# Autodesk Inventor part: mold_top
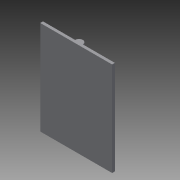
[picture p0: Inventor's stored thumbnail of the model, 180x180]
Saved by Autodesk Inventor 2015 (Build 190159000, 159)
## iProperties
Created: 2015-04
Part Number: mold_top
Material: Generic
Document SubType Name: Modeling
Designer: sungeun
Density: 1 g/cm^3
Appearance: Default
Author: sungeun
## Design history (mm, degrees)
sketch "Sketch1"
  geometry: L1 (-65, -2.5)-(65, -2.5); L2 (65, -2.5)-(65, 2.5); L3 (65, 2.5)-(-65, 2.5); L4 (-65, 2.5)-(-65, -2.5); L5 (-65, -2.5)-(65, 2.5); L6 (65, -2.5)-(-65, 2.5); 1 further point
  constraints: 12 end point, 2 midpoint, 2 parallel, 1 horizontal, 1 perpendicular
  dimensions: "d0" = 130 distance of L2.end L3.end; "d1" = 5 distance of L1.end L2.end
extrude "Extrusion1" new body sketch "Sketch1" stored distance "d2" = 170; taper "d3" = 0 deg
sketch "Sketch2" dims "d20" = 65, "d21" = 45
  geometry: L1 (65, 150)-(65, 20); 2 further points; 1 other entity
  constraints: 2 end point, 1 coincident, 1 vertical, 4 other
  dimensions: "d27" = 130 distance of L1.start L1.end
sketch "Sketch3"
  geometry: L1 (130, 170)-(130, 0) reference; L2 (115, 147.5)-(115, 162.5); A1 r 7.5 centre (115, 155) between (115, 147.5) and (115, 162.5); 1 further point
  constraints: 2 end point, 2 point on circle, 1 centre point, 1 vertical
  dimensions: "d6" = 70 vertical distance of point (65, 85) A1.centre; "d7" = 50 horizontal distance of point (65, 85) A1.centre; "d8" = 15 diameter of A1; "d9" = 15 distance of L2.start L2.end
revolve "Revolution2" sketch "Sketch3" stored, may be unused: angle "d10" = 180 deg
pattern_linear "Rectangular Pattern1" dims "d13" = 135
revolve "Revolution3" stored, may be unused: angle "d23" = 180 deg
sketch "Sketch5"
  geometry: L1 (65, 2.5)-(-65, 2.5) reference; L2 (-7, 2.5)-(7, 2.5); A1 r 7 centre (0, 2.5) between (7, 2.5) and (-7, 2.5)
  constraints: 2 end point, 2 point on circle, 1 centre point, 1 collinear, 1 midpoint, 1 point on line
  dimensions: "d31" = 7 radius of A1
extrude "Extrusion3" join sketch "Sketch5" distance "d25" = 155; taper "d26" = 0 deg
body "Solid1"
